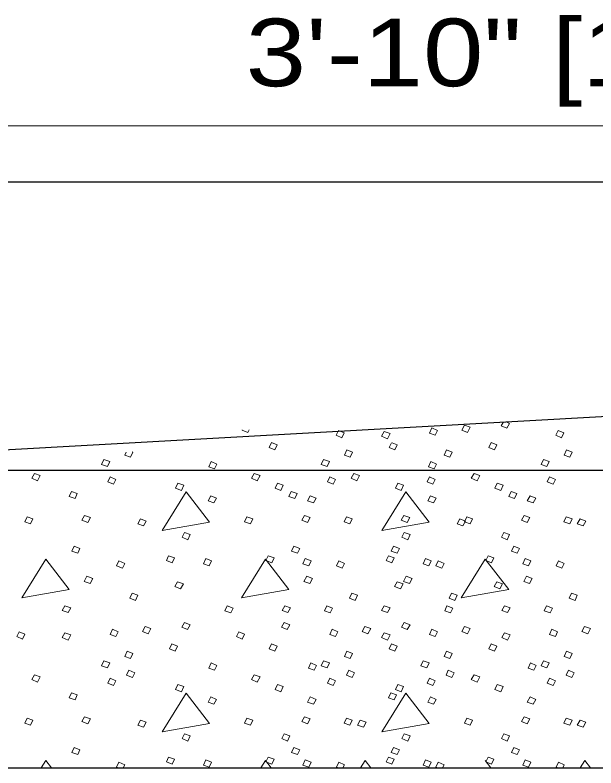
# Model space of a CAD drawing. Extents: x -1431.2 to -1397.2, y -1045.1 to -1001.1.
# Drawn here: x -1424.925 to -1423.56, y -1043.619 to -1041.85 of the extents above; entities that cross this region are included whole.
import ezdxf

# ---------------------------------------------------------------- set-up
doc = ezdxf.new("R2010")
doc.units = 0
doc.header["$LTSCALE"] = 0.064
doc.layers.add('1', color=7, linetype='Continuous', lineweight=13)

msp = doc.modelspace()

# ---------------------------------------------------------------- linework, layer by layer
at = {"layer": '1'}
for p, q in [((-1421.35642, -1042.111), (-1425.81283, -1042.111)), ((-1424.85325, -1043.60183), (-1424.86408, -1043.61933)), ((-1424.83958, -1043.61933), (-1424.85325, -1043.60183)), ((-1424.33667, -1043.60183), (-1424.34758, -1043.61933)), ((-1424.32308, -1043.61933), (-1424.33667, -1043.60183)), ((-1424.10258, -1043.60183), (-1424.1135, -1043.61933)), ((-1424.089, -1043.61933), (-1424.10258, -1043.60183)), ((-1423.80658, -1043.61933), (-1423.82017, -1043.60183)), ((-1423.58608, -1043.60183), (-1423.59692, -1043.61933)), ((-1423.5725, -1043.61933), (-1423.58608, -1043.60183))]:
    msp.add_line(p, q, dxfattribs=at)
at = {"layer": '1', "lineweight": 25}
for p, q in [((-1425.81283, -1042.9205), (-1422.42375, -1042.73033)), ((-1420.649, -1042.9205), (-1425.81283, -1042.9205))]:
    msp.add_line(p, q, dxfattribs=at)
for points in [[(-1421.35642, -1042.24275), (-1422.37992, -1042.24275), (-1425.79833, -1042.24275)], [(-1426.53858, -1043.13475), (-1426.53858, -1043.61933), (-1420.649, -1043.61933)]]:
    msp.add_lwpolyline(points, dxfattribs=at)
at = {"layer": '1'}
for points in [[(-1423.86883, -1042.81408), (-1423.85517, -1042.819), (-1423.86158, -1042.83125), (-1423.87517, -1042.8255)], [(-1424.16508, -1042.82633), (-1424.1515, -1042.832), (-1424.157, -1042.84342), (-1424.17058, -1042.83775)], [(-1424.05725, -1042.82875), (-1424.04367, -1042.83367), (-1424.05, -1042.84592), (-1424.06367, -1042.84017)], [(-1423.94583, -1042.82058), (-1423.93225, -1042.82633), (-1423.93767, -1042.83775), (-1423.95125, -1042.83283)], [(-1423.64858, -1042.82633), (-1423.635, -1042.832), (-1423.64042, -1042.84342), (-1423.654, -1042.83775)], [(-1424.32275, -1042.85483), (-1424.30917, -1042.86058), (-1424.31467, -1042.872), (-1424.32825, -1042.86625)], [(-1423.80625, -1042.85483), (-1423.79267, -1042.86058), (-1423.79808, -1042.872), (-1423.81167, -1042.86625)], [(-1424.1455, -1042.872), (-1424.13192, -1042.87767), (-1424.13733, -1042.88908), (-1424.15092, -1042.88425)], [(-1423.91142, -1042.872), (-1423.89783, -1042.87767), (-1423.90325, -1042.88908), (-1423.91683, -1042.88425)], [(-1423.629, -1042.872), (-1423.61533, -1042.87767), (-1423.62083, -1042.88908), (-1423.63442, -1042.88425)], [(-1424.71633, -1042.89483), (-1424.70275, -1042.89975), (-1424.70825, -1042.91117), (-1424.72183, -1042.90625)], [(-1424.4645, -1042.89975), (-1424.45083, -1042.90542), (-1424.45633, -1042.91683), (-1424.46992, -1042.91192)], [(-1424.19983, -1042.89483), (-1424.18625, -1042.89975), (-1424.19167, -1042.91117), (-1424.20533, -1042.90625)], [(-1423.94792, -1042.89975), (-1423.93433, -1042.90542), (-1423.93975, -1042.91683), (-1423.95333, -1042.91192)], [(-1423.68333, -1042.89483), (-1423.66975, -1042.89975), (-1423.67517, -1042.91117), (-1423.68875, -1042.90625)], [(-1424.8795, -1042.92742), (-1424.86592, -1042.93233), (-1424.87225, -1042.94458), (-1424.88583, -1042.93883)], [(-1424.70183, -1042.93558), (-1424.68825, -1042.94133), (-1424.69375, -1042.95275), (-1424.70733, -1042.947)], [(-1424.363, -1042.92742), (-1424.34933, -1042.93233), (-1424.35575, -1042.94458), (-1424.36933, -1042.93883)], [(-1424.18533, -1042.93558), (-1424.17175, -1042.94133), (-1424.17717, -1042.95275), (-1424.19075, -1042.947)], [(-1424.12883, -1042.92742), (-1424.11525, -1042.93233), (-1424.12158, -1042.94458), (-1424.13517, -1042.93883)], [(-1423.95125, -1042.93558), (-1423.93767, -1042.94133), (-1423.94308, -1042.95275), (-1423.95667, -1042.947)], [(-1423.84642, -1042.92742), (-1423.83283, -1042.93233), (-1423.83917, -1042.94458), (-1423.85275, -1042.93883)], [(-1423.66883, -1042.93558), (-1423.65525, -1042.94133), (-1423.66067, -1042.95275), (-1423.67425, -1042.947)], [(-1424.54242, -1042.95025), (-1424.52883, -1042.95517), (-1424.53425, -1042.96742), (-1424.54783, -1042.96167)], [(-1424.30825, -1042.95025), (-1424.29467, -1042.95517), (-1424.30017, -1042.96742), (-1424.31375, -1042.96167)], [(-1424.02583, -1042.95025), (-1424.01225, -1042.95517), (-1424.01775, -1042.96742), (-1424.03133, -1042.96167)], [(-1423.79175, -1042.95025), (-1423.77817, -1042.95517), (-1423.78358, -1042.96742), (-1423.79717, -1042.96167)], [(-1424.7925, -1042.96983), (-1424.77892, -1042.97475), (-1424.78433, -1042.98617), (-1424.79792, -1042.98125)], [(-1424.52333, -1042.97067), (-1424.5795, -1043.06117), (-1424.46808, -1043.04158)], [(-1424.276, -1042.96983), (-1424.26242, -1042.97475), (-1424.26783, -1042.98617), (-1424.28142, -1042.98125)], [(-1424.00683, -1042.97067), (-1424.063, -1043.06117), (-1423.95158, -1043.04158)], [(-1423.75942, -1042.96983), (-1423.74583, -1042.97475), (-1423.75125, -1042.98617), (-1423.76492, -1042.98125)], [(-1424.46533, -1042.97967), (-1424.45175, -1042.98533), (-1424.45808, -1042.99675), (-1424.47167, -1042.99183)], [(-1424.23125, -1042.97967), (-1424.21767, -1042.98533), (-1424.224, -1042.99675), (-1424.23758, -1042.99183)], [(-1423.94883, -1042.97967), (-1423.93525, -1042.98533), (-1423.94158, -1042.99675), (-1423.95517, -1042.99183)], [(-1423.71475, -1042.97967), (-1423.70117, -1042.98533), (-1423.7075, -1042.99675), (-1423.72108, -1042.99183)], [(-1424.76167, -1043.02608), (-1424.74808, -1043.031), (-1424.75442, -1043.04242), (-1424.768, -1043.0375)], [(-1424.24517, -1043.02608), (-1424.23158, -1043.031), (-1424.23792, -1043.04242), (-1424.2515, -1043.0375)], [(-1424.01108, -1043.02608), (-1423.9975, -1043.031), (-1424.00383, -1043.04242), (-1424.01742, -1043.0375)], [(-1423.72867, -1043.02608), (-1423.715, -1043.031), (-1423.72142, -1043.04242), (-1423.735, -1043.0375)], [(-1424.89675, -1043.02942), (-1424.88308, -1043.03425), (-1424.88858, -1043.04567), (-1424.90217, -1043.04083)], [(-1424.63025, -1043.03425), (-1424.61667, -1043.03917), (-1424.623, -1043.05058), (-1424.63667, -1043.04567)], [(-1424.38017, -1043.02942), (-1424.36658, -1043.03425), (-1424.372, -1043.04567), (-1424.38558, -1043.04083)], [(-1424.14608, -1043.02942), (-1424.1325, -1043.03425), (-1424.13792, -1043.04567), (-1424.1515, -1043.04083)], [(-1423.87967, -1043.03425), (-1423.86608, -1043.03917), (-1423.87242, -1043.05058), (-1423.886, -1043.04567)], [(-1423.86367, -1043.02942), (-1423.85008, -1043.03425), (-1423.8555, -1043.04567), (-1423.86908, -1043.04083)], [(-1423.62958, -1043.02942), (-1423.616, -1043.03425), (-1423.62142, -1043.04567), (-1423.635, -1043.04083)], [(-1423.59725, -1043.03425), (-1423.58367, -1043.03917), (-1423.59, -1043.05058), (-1423.60358, -1043.04567)], [(-1424.527, -1043.06608), (-1424.51342, -1043.071), (-1424.51883, -1043.08317), (-1424.53242, -1043.0775)], [(-1424.01042, -1043.06608), (-1423.99683, -1043.071), (-1424.00233, -1043.08317), (-1424.01592, -1043.0775)], [(-1423.77633, -1043.06608), (-1423.76275, -1043.071), (-1423.76817, -1043.08317), (-1423.78183, -1043.0775)], [(-1424.78617, -1043.09867), (-1424.77258, -1043.10358), (-1424.778, -1043.115), (-1424.79158, -1043.11008)], [(-1424.26958, -1043.09867), (-1424.256, -1043.10358), (-1424.2615, -1043.115), (-1424.27508, -1043.11008)], [(-1424.0355, -1043.09867), (-1424.02192, -1043.10358), (-1424.02733, -1043.115), (-1424.041, -1043.11008)], [(-1423.75308, -1043.09867), (-1423.7395, -1043.10358), (-1423.74492, -1043.115), (-1423.75858, -1043.11008)], [(-1424.85325, -1043.12883), (-1424.90942, -1043.21942), (-1424.79792, -1043.19983)], [(-1424.681, -1043.13292), (-1424.66742, -1043.13867), (-1424.67292, -1043.15008), (-1424.6865, -1043.14433)], [(-1424.56417, -1043.12075), (-1424.55058, -1043.12558), (-1424.556, -1043.13783), (-1424.56958, -1043.13217)], [(-1424.47717, -1043.12725), (-1424.46358, -1043.13292), (-1424.469, -1043.14433), (-1424.48258, -1043.1395)], [(-1424.33667, -1043.12883), (-1424.39283, -1043.21942), (-1424.28142, -1043.19983)], [(-1424.33008, -1043.12075), (-1424.31642, -1043.12558), (-1424.32192, -1043.13783), (-1424.3355, -1043.13217)], [(-1424.24308, -1043.12725), (-1424.22942, -1043.13292), (-1424.23492, -1043.14433), (-1424.2485, -1043.1395)], [(-1424.1645, -1043.13292), (-1424.15092, -1043.13867), (-1424.15633, -1043.15008), (-1424.16992, -1043.14433)], [(-1424.04758, -1043.12075), (-1424.034, -1043.12558), (-1424.03942, -1043.13783), (-1424.05308, -1043.13217)], [(-1423.96058, -1043.12725), (-1423.947, -1043.13292), (-1423.9525, -1043.14433), (-1423.96608, -1043.1395)], [(-1423.93042, -1043.13292), (-1423.91683, -1043.13867), (-1423.92225, -1043.15008), (-1423.93583, -1043.14433)], [(-1423.82017, -1043.12883), (-1423.87633, -1043.21942), (-1423.76492, -1043.19983)], [(-1423.8135, -1043.12075), (-1423.79992, -1043.12558), (-1423.80533, -1043.13783), (-1423.81892, -1043.13217)], [(-1423.7265, -1043.12725), (-1423.71292, -1043.13292), (-1423.71833, -1043.14433), (-1423.732, -1043.1395)], [(-1423.648, -1043.13292), (-1423.63442, -1043.13867), (-1423.63983, -1043.15008), (-1423.65342, -1043.14433)], [(-1424.75625, -1043.16883), (-1424.74267, -1043.17458), (-1424.749, -1043.186), (-1424.76258, -1043.18108)], [(-1424.23975, -1043.16883), (-1424.22617, -1043.17458), (-1424.2325, -1043.186), (-1424.24608, -1043.18108)], [(-1424.00567, -1043.16883), (-1423.992, -1043.17458), (-1423.99833, -1043.186), (-1424.012, -1043.18108)], [(-1423.72317, -1043.16883), (-1423.70958, -1043.17458), (-1423.71592, -1043.186), (-1423.72958, -1043.18108)], [(-1424.54333, -1043.18192), (-1424.52967, -1043.18675), (-1424.53608, -1043.19817), (-1424.54967, -1043.19325)], [(-1424.02675, -1043.18192), (-1424.01317, -1043.18675), (-1424.0195, -1043.19817), (-1424.03308, -1043.19325)], [(-1423.79267, -1043.18192), (-1423.77908, -1043.18675), (-1423.78542, -1043.19817), (-1423.799, -1043.19325)], [(-1424.65025, -1043.20875), (-1424.63667, -1043.21367), (-1424.64208, -1043.22592), (-1424.65567, -1043.22025)], [(-1424.13367, -1043.20875), (-1424.12008, -1043.21367), (-1424.12558, -1043.22592), (-1424.13917, -1043.22025)], [(-1423.89958, -1043.20875), (-1423.886, -1043.21367), (-1423.89142, -1043.22592), (-1423.905, -1043.22025)], [(-1423.61717, -1043.20875), (-1423.60358, -1043.21367), (-1423.609, -1043.22592), (-1423.62258, -1043.22025)], [(-1424.80792, -1043.23817), (-1424.79433, -1043.243), (-1424.80067, -1043.25442), (-1424.81425, -1043.24958)], [(-1424.42642, -1043.23817), (-1424.41283, -1043.24383), (-1424.41825, -1043.25525), (-1424.43183, -1043.25042)], [(-1424.29133, -1043.23817), (-1424.27775, -1043.243), (-1424.28408, -1043.25442), (-1424.29775, -1043.24958)], [(-1424.19233, -1043.23817), (-1424.17875, -1043.24383), (-1424.18417, -1043.25525), (-1424.19775, -1043.25042)], [(-1424.05725, -1043.23817), (-1424.04367, -1043.243), (-1424.05, -1043.25442), (-1424.06367, -1043.24958)], [(-1423.90992, -1043.23817), (-1423.89625, -1043.24383), (-1423.90175, -1043.25525), (-1423.91533, -1043.25042)], [(-1423.77483, -1043.23817), (-1423.76125, -1043.243), (-1423.76758, -1043.25442), (-1423.78117, -1043.24958)], [(-1423.67575, -1043.23817), (-1423.66217, -1043.24383), (-1423.66758, -1043.25525), (-1423.68125, -1043.25042)], [(-1424.61942, -1043.28708), (-1424.60583, -1043.292), (-1424.61217, -1043.30417), (-1424.62575, -1043.2985)], [(-1424.527, -1043.27725), (-1424.51342, -1043.283), (-1424.51975, -1043.29442), (-1424.53333, -1043.28867)], [(-1424.29292, -1043.27725), (-1424.27933, -1043.283), (-1424.28567, -1043.29442), (-1424.29925, -1043.28867)], [(-1424.10292, -1043.28708), (-1424.08933, -1043.292), (-1424.09567, -1043.30417), (-1424.10925, -1043.2985)], [(-1424.01042, -1043.27725), (-1423.99683, -1043.283), (-1424.00325, -1043.29442), (-1424.01683, -1043.28867)], [(-1423.86883, -1043.28708), (-1423.85517, -1043.292), (-1423.86158, -1043.30417), (-1423.87517, -1043.2985)], [(-1423.58633, -1043.28708), (-1423.57275, -1043.292), (-1423.57908, -1043.30417), (-1423.59267, -1043.2985)], [(-1424.91575, -1043.29933), (-1424.90217, -1043.305), (-1424.90758, -1043.31642), (-1424.92117, -1043.31075)], [(-1424.80792, -1043.30175), (-1424.79433, -1043.30667), (-1424.80067, -1043.31892), (-1424.81425, -1043.31317)], [(-1424.69642, -1043.29358), (-1424.68283, -1043.29933), (-1424.68825, -1043.31075), (-1424.70183, -1043.30583)], [(-1424.39925, -1043.29933), (-1424.38558, -1043.305), (-1424.39108, -1043.31642), (-1424.40467, -1043.31075)], [(-1424.17992, -1043.29358), (-1424.16633, -1043.29933), (-1424.17175, -1043.31075), (-1424.18533, -1043.30583)], [(-1424.05725, -1043.30175), (-1424.04367, -1043.30667), (-1424.05, -1043.31892), (-1424.06367, -1043.31317)], [(-1423.94583, -1043.29358), (-1423.93225, -1043.29933), (-1423.93767, -1043.31075), (-1423.95125, -1043.30583)], [(-1423.77483, -1043.30175), (-1423.76125, -1043.30667), (-1423.76758, -1043.31892), (-1423.78117, -1043.31317)], [(-1423.66342, -1043.29358), (-1423.64983, -1043.29933), (-1423.65525, -1043.31075), (-1423.66883, -1043.30583)], [(-1424.55692, -1043.32783), (-1424.54333, -1043.33358), (-1424.54875, -1043.345), (-1424.56233, -1043.33925)], [(-1424.32275, -1043.32783), (-1424.30917, -1043.33358), (-1424.31467, -1043.345), (-1424.32825, -1043.33925)], [(-1424.04033, -1043.32783), (-1424.02675, -1043.33358), (-1424.03225, -1043.345), (-1424.04583, -1043.33925)], [(-1423.80625, -1043.32783), (-1423.79267, -1043.33358), (-1423.79808, -1043.345), (-1423.81167, -1043.33925)], [(-1424.662, -1043.345), (-1424.64842, -1043.35067), (-1424.65383, -1043.36208), (-1424.66742, -1043.35717)], [(-1424.1455, -1043.345), (-1424.13192, -1043.35067), (-1424.13733, -1043.36208), (-1424.15092, -1043.35717)], [(-1423.91142, -1043.345), (-1423.89783, -1043.35067), (-1423.90325, -1043.36208), (-1423.91683, -1043.35717)], [(-1423.629, -1043.345), (-1423.61533, -1043.35067), (-1423.62083, -1043.36208), (-1423.63442, -1043.35717)], [(-1424.71633, -1043.36783), (-1424.70275, -1043.37267), (-1424.70825, -1043.38408), (-1424.72183, -1043.37925)], [(-1424.4645, -1043.37267), (-1424.45083, -1043.37842), (-1424.45633, -1043.38983), (-1424.46992, -1043.38492)], [(-1424.23033, -1043.37267), (-1424.21675, -1043.37842), (-1424.22217, -1043.38983), (-1424.23583, -1043.38492)], [(-1424.19983, -1043.36783), (-1424.18625, -1043.37267), (-1424.19167, -1043.38408), (-1424.20533, -1043.37925)], [(-1423.96575, -1043.36783), (-1423.95217, -1043.37267), (-1423.95758, -1043.38408), (-1423.97117, -1043.37925)], [(-1423.71383, -1043.37267), (-1423.70025, -1043.37842), (-1423.70567, -1043.38983), (-1423.71925, -1043.38492)], [(-1423.68333, -1043.36783), (-1423.66975, -1043.37267), (-1423.67517, -1043.38408), (-1423.68875, -1043.37925)], [(-1424.6575, -1043.38983), (-1424.64392, -1043.3955), (-1424.64933, -1043.40692), (-1424.66292, -1043.40125)], [(-1424.14092, -1043.38983), (-1424.12733, -1043.3955), (-1424.13275, -1043.40692), (-1424.14642, -1043.40125)], [(-1423.90683, -1043.38983), (-1423.89325, -1043.3955), (-1423.89867, -1043.40692), (-1423.91225, -1043.40125)], [(-1423.62442, -1043.38983), (-1423.61083, -1043.3955), (-1423.61625, -1043.40692), (-1423.62983, -1043.40125)], [(-1424.8795, -1043.40042), (-1424.86592, -1043.40533), (-1424.87225, -1043.41758), (-1424.88583, -1043.41183)], [(-1424.70183, -1043.40858), (-1424.68825, -1043.41433), (-1424.69375, -1043.42575), (-1424.70733, -1043.42)], [(-1424.363, -1043.40042), (-1424.34933, -1043.40533), (-1424.35575, -1043.41758), (-1424.36933, -1043.41183)], [(-1424.18533, -1043.40858), (-1424.17175, -1043.41433), (-1424.17717, -1043.42575), (-1424.19075, -1043.42)], [(-1423.95125, -1043.40858), (-1423.93767, -1043.41433), (-1423.94308, -1043.42575), (-1423.95667, -1043.42)], [(-1423.84642, -1043.40042), (-1423.83283, -1043.40533), (-1423.83917, -1043.41758), (-1423.85275, -1043.41183)], [(-1423.66883, -1043.40858), (-1423.65525, -1043.41433), (-1423.66067, -1043.42575), (-1423.67425, -1043.42)], [(-1424.54242, -1043.42325), (-1424.52883, -1043.42817), (-1424.53425, -1043.44042), (-1424.54783, -1043.43467)], [(-1424.30825, -1043.42325), (-1424.29467, -1043.42817), (-1424.30017, -1043.44042), (-1424.31375, -1043.43467)], [(-1424.02583, -1043.42325), (-1424.01225, -1043.42817), (-1424.01775, -1043.44042), (-1424.03133, -1043.43467)], [(-1423.79175, -1043.42325), (-1423.77817, -1043.42817), (-1423.78358, -1043.44042), (-1423.79717, -1043.43467)], [(-1424.7925, -1043.44283), (-1424.77892, -1043.44775), (-1424.78433, -1043.45917), (-1424.79792, -1043.45425)], [(-1424.52333, -1043.44367), (-1424.5795, -1043.53417), (-1424.46808, -1043.51458)], [(-1424.00683, -1043.44367), (-1424.063, -1043.53417), (-1423.95158, -1043.51458)], [(-1424.04183, -1043.44283), (-1424.02825, -1043.44775), (-1424.03375, -1043.45917), (-1424.04733, -1043.45425)], [(-1424.46533, -1043.45258), (-1424.45175, -1043.45833), (-1424.45808, -1043.46975), (-1424.47167, -1043.46483)], [(-1424.23125, -1043.45258), (-1424.21767, -1043.45833), (-1424.224, -1043.46975), (-1424.23758, -1043.46483)], [(-1423.94883, -1043.45258), (-1423.93525, -1043.45833), (-1423.94158, -1043.46975), (-1423.95517, -1043.46483)], [(-1423.71475, -1043.45258), (-1423.70117, -1043.45833), (-1423.7075, -1043.46975), (-1423.72108, -1043.46483)], [(-1424.89675, -1043.50233), (-1424.88308, -1043.50725), (-1424.88858, -1043.51867), (-1424.90217, -1043.51375)], [(-1424.76167, -1043.49908), (-1424.74808, -1043.504), (-1424.75442, -1043.51542), (-1424.768, -1043.5105)], [(-1424.38017, -1043.50233), (-1424.36658, -1043.50725), (-1424.372, -1043.51867), (-1424.38558, -1043.51375)], [(-1424.24517, -1043.49908), (-1424.23158, -1043.504), (-1424.23792, -1043.51542), (-1424.2515, -1043.5105)], [(-1424.14608, -1043.50233), (-1424.1325, -1043.50725), (-1424.13792, -1043.51867), (-1424.1515, -1043.51375)], [(-1423.86367, -1043.50233), (-1423.85008, -1043.50725), (-1423.8555, -1043.51867), (-1423.86908, -1043.51375)], [(-1423.72867, -1043.49908), (-1423.715, -1043.504), (-1423.72142, -1043.51542), (-1423.735, -1043.5105)], [(-1423.62958, -1043.50233), (-1423.616, -1043.50725), (-1423.62142, -1043.51867), (-1423.635, -1043.51375)], [(-1424.63025, -1043.50725), (-1424.61667, -1043.51217), (-1424.623, -1043.52358), (-1424.63667, -1043.51867)], [(-1424.11375, -1043.50725), (-1424.10017, -1043.51217), (-1424.1065, -1043.52358), (-1424.12008, -1043.51867)], [(-1423.59725, -1043.50725), (-1423.58367, -1043.51217), (-1423.59, -1043.52358), (-1423.60358, -1043.51867)], [(-1424.527, -1043.53908), (-1424.51342, -1043.54392), (-1424.51883, -1043.55617), (-1424.53242, -1043.5505)], [(-1424.29292, -1043.53908), (-1424.27933, -1043.54392), (-1424.28475, -1043.55617), (-1424.29833, -1043.5505)], [(-1424.01042, -1043.53908), (-1423.99683, -1043.54392), (-1424.00233, -1043.55617), (-1424.01592, -1043.5505)], [(-1423.77633, -1043.53908), (-1423.76275, -1043.54392), (-1423.76817, -1043.55617), (-1423.78183, -1043.5505)], [(-1424.78617, -1043.57167), (-1424.77258, -1043.57658), (-1424.778, -1043.588), (-1424.79158, -1043.58308)], [(-1424.26958, -1043.57167), (-1424.256, -1043.57658), (-1424.2615, -1043.588), (-1424.27508, -1043.58308)], [(-1424.0355, -1043.57167), (-1424.02192, -1043.57658), (-1424.02733, -1043.588), (-1424.041, -1043.58308)], [(-1423.75308, -1043.57167), (-1423.7395, -1043.57658), (-1423.74492, -1043.588), (-1423.75858, -1043.58308)], [(-1424.56417, -1043.59367), (-1424.55058, -1043.59858), (-1424.556, -1043.61083), (-1424.56958, -1043.60508)], [(-1424.47717, -1043.60025), (-1424.46358, -1043.60592), (-1424.469, -1043.61733), (-1424.48258, -1043.61242)], [(-1424.33008, -1043.59367), (-1424.31642, -1043.59858), (-1424.32192, -1043.61083), (-1424.3355, -1043.60508)], [(-1424.24308, -1043.60025), (-1424.22942, -1043.60592), (-1424.23492, -1043.61733), (-1424.2485, -1043.61242)], [(-1424.04758, -1043.59367), (-1424.034, -1043.59858), (-1424.03942, -1043.61083), (-1424.05308, -1043.60508)], [(-1423.96058, -1043.60025), (-1423.947, -1043.60592), (-1423.9525, -1043.61733), (-1423.96608, -1043.61242)], [(-1423.8135, -1043.59367), (-1423.79992, -1043.59858), (-1423.80533, -1043.61083), (-1423.81892, -1043.60508)], [(-1423.7265, -1043.60025), (-1423.71292, -1043.60592), (-1423.71833, -1043.61733), (-1423.732, -1043.61242)]]:
    msp.add_lwpolyline(points, close=True, dxfattribs=at)
for points in [[(-1423.76908, -1042.80733), (-1423.76275, -1042.81), (-1423.76908, -1042.82142), (-1423.78267, -1042.81575), (-1423.77817, -1042.80767)], [(-1424.37475, -1042.82467), (-1424.37808, -1042.83125), (-1424.39167, -1042.8255), (-1424.3915, -1042.82517)], [(-1424.039, -1042.85542), (-1424.02675, -1042.86058), (-1424.03225, -1042.872), (-1424.04583, -1042.86625), (-1424.04067, -1042.8555)], [(-1424.65033, -1042.87692), (-1424.64842, -1042.87767), (-1424.65383, -1042.88908), (-1424.66742, -1042.88425), (-1424.66442, -1042.87742)], [(-1424.68183, -1043.61933), (-1424.6865, -1043.61733), (-1424.681, -1043.60592)], [(-1424.681, -1043.60592), (-1424.66742, -1043.61167), (-1424.67108, -1043.61933)], [(-1424.16533, -1043.61933), (-1424.16992, -1043.61733), (-1424.1645, -1043.60592)], [(-1424.1645, -1043.60592), (-1424.15092, -1043.61167), (-1424.1545, -1043.61933)], [(-1423.93125, -1043.61933), (-1423.93583, -1043.61733), (-1423.93042, -1043.60592)], [(-1423.93042, -1043.60592), (-1423.91683, -1043.61167), (-1423.92042, -1043.61933)], [(-1423.64883, -1043.61933), (-1423.65342, -1043.61733), (-1423.648, -1043.60592)], [(-1423.648, -1043.60592), (-1423.63442, -1043.61167), (-1423.638, -1043.61933)]]:
    msp.add_lwpolyline(points, dxfattribs=at)

# ---------------------------------------------------------------- texts
at = {"layer": '1', "width": 1.2}
msp.add_text('3\'-10" [1150]', height=0.1588, dxfattribs=at).set_placement((-1424.383, -1042.01775))

doc.saveas('drawing.dxf')
